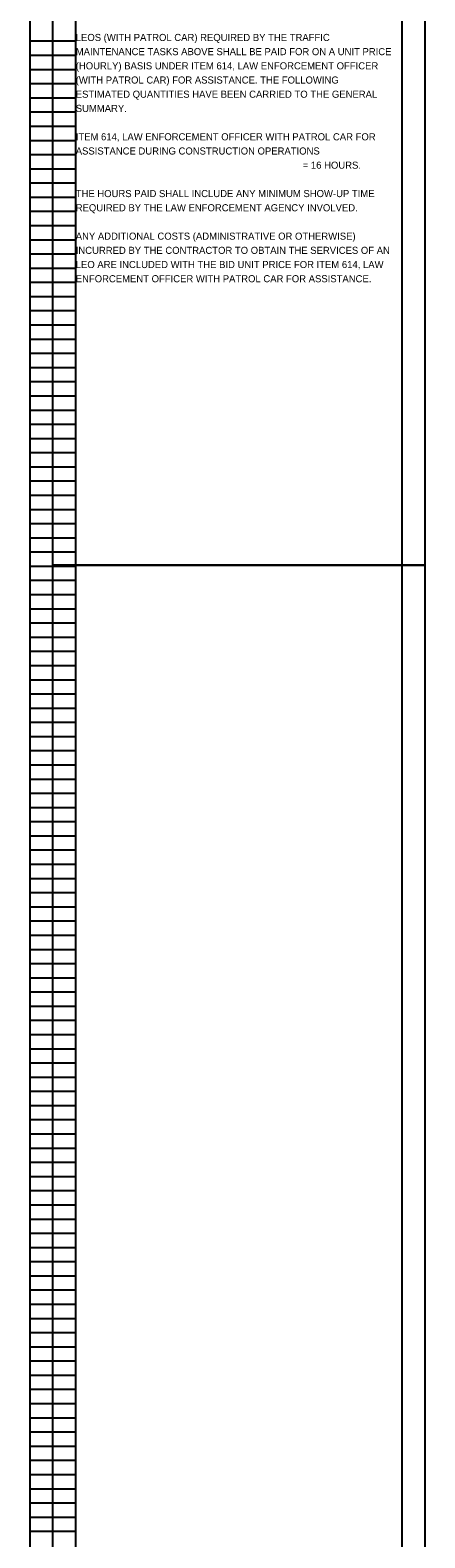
# Model space of a CAD drawing. Extents: x -13 to 29, y -301 to 22.
# Drawn here: x 1.5 to 9.29, y -139.15 to -109.41 of the extents above; entities that cross this region are included whole.
import ezdxf

# ---------------------------------------------------------------- set-up
doc = ezdxf.new("R2010")
doc.units = 0
doc.layers.add('SC_Scratch1', color=7, linetype='Continuous')
doc.layers.add('SH_Text', color=7, linetype='Continuous')

msp = doc.modelspace()

# ---------------------------------------------------------------- linework, layer by layer
at = {"layer": 'SH_Text'}
for p, q in [((1.5, -119.98), (1.5, -99.82)), ((2.4, -119.98), (2.4, -99.82)), ((8.84, -119.98), (8.84, -99.82)), ((1.5, -109.62), (2.4, -109.62)), ((1.5, -109.9), (2.4, -109.9)), ((1.5, -110.18), (2.4, -110.18)), ((1.5, -110.46), (2.4, -110.46)), ((1.5, -110.74), (2.4, -110.74)), ((1.5, -111.02), (2.4, -111.02)), ((1.5, -111.3), (2.4, -111.3)), ((1.5, -111.58), (2.4, -111.58)), ((1.5, -111.86), (2.4, -111.86)), ((1.5, -112.14), (2.4, -112.14)), ((1.5, -112.42), (2.4, -112.42)), ((1.5, -112.7), (2.4, -112.7)), ((1.5, -112.98), (2.4, -112.98)), ((1.5, -113.26), (2.4, -113.26)), ((1.5, -113.54), (2.4, -113.54)), ((1.5, -113.82), (2.4, -113.82)), ((1.5, -114.1), (2.4, -114.1)), ((1.5, -114.38), (2.4, -114.38)), ((1.5, -114.66), (2.4, -114.66)), ((1.5, -114.94), (2.4, -114.94)), ((1.5, -115.22), (2.4, -115.22)), ((1.5, -115.5), (2.4, -115.5)), ((1.5, -115.78), (2.4, -115.78)), ((1.5, -116.06), (2.4, -116.06)), ((1.5, -116.34), (2.4, -116.34)), ((1.5, -116.62), (2.4, -116.62)), ((1.5, -116.9), (2.4, -116.9)), ((1.5, -117.18), (2.4, -117.18)), ((1.5, -117.46), (2.4, -117.46)), ((1.5, -117.74), (2.4, -117.74)), ((1.5, -118.02), (2.4, -118.02)), ((1.5, -118.3), (2.4, -118.3)), ((1.5, -118.58), (2.4, -118.58)), ((1.5, -118.86), (2.4, -118.86)), ((1.5, -119.14), (2.4, -119.14)), ((1.5, -119.42), (2.4, -119.42)), ((1.5, -119.7), (2.4, -119.7)), ((1.5, -119.98), (2.4, -119.98)), ((1.5, -119.98), (2.4, -119.98)), ((1.5, -140.14), (1.5, -119.98)), ((2.4, -140.14), (2.4, -119.98)), ((8.84, -140.14), (8.84, -119.98)), ((1.5, -120.26), (2.4, -120.26)), ((1.5, -120.54), (2.4, -120.54)), ((1.5, -120.82), (2.4, -120.82)), ((1.5, -121.1), (2.4, -121.1)), ((1.5, -121.38), (2.4, -121.38)), ((1.5, -121.66), (2.4, -121.66)), ((1.5, -121.94), (2.4, -121.94)), ((1.5, -122.22), (2.4, -122.22)), ((1.5, -122.5), (2.4, -122.5)), ((1.5, -122.78), (2.4, -122.78)), ((1.5, -123.06), (2.4, -123.06)), ((1.5, -123.34), (2.4, -123.34)), ((1.5, -123.62), (2.4, -123.62)), ((1.5, -123.9), (2.4, -123.9)), ((1.5, -124.18), (2.4, -124.18)), ((1.5, -124.46), (2.4, -124.46)), ((1.5, -124.74), (2.4, -124.74)), ((1.5, -125.02), (2.4, -125.02)), ((1.5, -125.3), (2.4, -125.3)), ((1.5, -125.58), (2.4, -125.58)), ((1.5, -125.86), (2.4, -125.86)), ((1.5, -126.14), (2.4, -126.14)), ((1.5, -126.42), (2.4, -126.42)), ((1.5, -126.7), (2.4, -126.7)), ((1.5, -126.98), (2.4, -126.98)), ((1.5, -127.26), (2.4, -127.26)), ((1.5, -127.54), (2.4, -127.54)), ((1.5, -127.82), (2.4, -127.82)), ((1.5, -128.1), (2.4, -128.1)), ((1.5, -128.38), (2.4, -128.38)), ((1.5, -128.66), (2.4, -128.66)), ((1.5, -128.94), (2.4, -128.94)), ((1.5, -129.22), (2.4, -129.22)), ((1.5, -129.5), (2.4, -129.5)), ((1.5, -129.78), (2.4, -129.78)), ((1.5, -130.06), (2.4, -130.06)), ((1.5, -130.34), (2.4, -130.34)), ((1.5, -130.62), (2.4, -130.62)), ((1.5, -130.9), (2.4, -130.9)), ((1.5, -131.18), (2.4, -131.18)), ((1.5, -131.46), (2.4, -131.46)), ((1.5, -131.74), (2.4, -131.74)), ((1.5, -132.02), (2.4, -132.02)), ((1.5, -132.3), (2.4, -132.3)), ((1.5, -132.58), (2.4, -132.58)), ((1.5, -132.86), (2.4, -132.86)), ((1.5, -133.14), (2.4, -133.14)), ((1.5, -133.42), (2.4, -133.42)), ((1.5, -133.7), (2.4, -133.7)), ((1.5, -133.98), (2.4, -133.98)), ((1.5, -134.26), (2.4, -134.26)), ((1.5, -134.54), (2.4, -134.54)), ((1.5, -134.82), (2.4, -134.82)), ((1.5, -135.1), (2.4, -135.1)), ((1.5, -135.38), (2.4, -135.38)), ((1.5, -135.66), (2.4, -135.66)), ((1.5, -135.94), (2.4, -135.94)), ((1.5, -136.22), (2.4, -136.22)), ((1.5, -136.5), (2.4, -136.5)), ((1.5, -136.78), (2.4, -136.78)), ((1.5, -137.06), (2.4, -137.06)), ((1.5, -137.34), (2.4, -137.34)), ((1.5, -137.62), (2.4, -137.62)), ((1.5, -137.9), (2.4, -137.9)), ((1.5, -138.18), (2.4, -138.18)), ((1.5, -138.46), (2.4, -138.46)), ((1.5, -138.74), (2.4, -138.74)), ((1.5, -139.02), (2.4, -139.02))]:
    msp.add_line(p, q, dxfattribs=at)
for points in [[(1.95, -99.803), (9.29, -99.803), (9.29, -119.963), (1.95, -119.963)], [(1.95, -119.963), (9.29, -119.963), (9.29, -140.123), (1.95, -140.123)]]:
    msp.add_lwpolyline(points, close=True, dxfattribs=at)

# ---------------------------------------------------------------- texts
at = {"layer": 'SC_Scratch1'}
for s, p in [('LEOS (WITH PATROL CAR) REQUIRED BY THE TRAFFIC ', (2.4, -109.62)), ('(HOURLY) BASIS UNDER ITEM 614, LAW ENFORCEMENT OFFICER ', (2.4, -110.18)), ('MAINTENANCE TASKS ABOVE SHALL BE PAID FOR ON A UNIT PRICE ', (2.4, -109.9)), ('(WITH PATROL CAR) FOR ASSISTANCE. THE FOLLOWING ', (2.4, -110.46)), ('ESTIMATED QUANTITIES HAVE BEEN CARRIED TO THE GENERAL ', (2.4, -110.74)), ('SUMMARY.', (2.4, -111.02)), ('ITEM 614, LAW ENFORCEMENT OFFICER WITH PATROL CAR FOR ', (2.4, -111.58)), ('ASSISTANCE DURING CONSTRUCTION OPERATIONS', (2.4, -111.86)), ('= 16 HOURS.', (6.88, -112.14)), ('THE HOURS PAID SHALL INCLUDE ANY MINIMUM SHOW-UP TIME ', (2.4, -112.7)), ('REQUIRED BY THE LAW ENFORCEMENT AGENCY INVOLVED.', (2.4, -112.98)), ('ANY ADDITIONAL COSTS (ADMINISTRATIVE OR OTHERWISE) ', (2.4, -113.54)), ('INCURRED BY THE CONTRACTOR TO OBTAIN THE SERVICES OF AN ', (2.4, -113.82)), ('LEO ARE INCLUDED WITH THE BID UNIT PRICE FOR ITEM 614, LAW ', (2.4, -114.1)), ('ENFORCEMENT OFFICER WITH PATROL CAR FOR ASSISTANCE.', (2.4, -114.38))]:
    msp.add_text(s, height=0.14, dxfattribs=at).set_placement(p)

doc.saveas('drawing.dxf')
